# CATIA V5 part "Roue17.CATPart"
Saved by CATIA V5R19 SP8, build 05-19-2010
Part number: Roue17
Bounding box of the stored display mesh (mm): x -150 to -130, y -107.421 to -47.421, z 104.667 to 164.667
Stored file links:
  G:\EU_thinkMotion\CFAO_2010\MMS_groupe2\MMS_groupe2\A reprendre\jcauchy\Roue17.CATPart
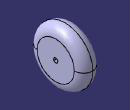
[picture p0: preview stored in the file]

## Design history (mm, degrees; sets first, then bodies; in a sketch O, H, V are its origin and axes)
Parameters
  Rayonroue_roue17 = 30 mm
  Rayonconge_roue17 = 10 mm
  Rayonfixation_roue17 = 2.5 mm
  Largeurroue_roue17 = 10 mm
Set1
  Plane1: stored without definition
  Sketch1 on Plane1, origin (-140, 0, 0), H (0, 1, 0), V (0, 0, 1)
    circle A1 centre (-77.4209, 134.6673) radius 30
    point P1 (-77.4209, 134.6673)
    reference projected point E1 (-77.4209, 134.6673) from Point1
    radius A1 = 30 {= Rayonroue_roue17}
    distance E1 P1 = 0
  Point1: stored without definition
Body1 (main body)
  Pad1: profile Sketch1, direction (1, 0, 0), length 10 {= Largeurroue_roue17}, mirrored extent
  Fillet1: radius 10 {= Rayonconge_roue17}, on edge [start face of Pad1 | face of Pad1 from Sketch1.A1]
  Fillet2: radius 10 {= Rayonconge_roue17}, on edge [face of Pad1 from Sketch1.A1 | end face of Pad1]
  Sketch2 on start face of Pad1, origin (-150, -77.4209, 134.6673), H (0, 1, 0), V (0, 0, -1)
    point P1 (0, 0)
  Hole1: placed by Sketch2, at (-150, -77.4209, 134.6673) direction (1, 0, 0), diameter 5 {= Rayonfixation_roue17 *2}, through (limit type 3)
